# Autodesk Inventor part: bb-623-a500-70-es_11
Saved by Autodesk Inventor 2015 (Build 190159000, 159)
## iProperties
Created: 2022-04
Part Number: bb-623-a500-70-es_11
Checked By: TraceParts S.A.
Material: Generic
Catalog Web Link: www.traceparts.com
Document SubType Name: Modeling
Designer: TraceParts
Density: 1 g/cm^3
Appearance: Default
Company: TraceParts S.A.
Author: TraceParts
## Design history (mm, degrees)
feature "bb-623-a500-70-es_11.ipt"
body "Solid1"
